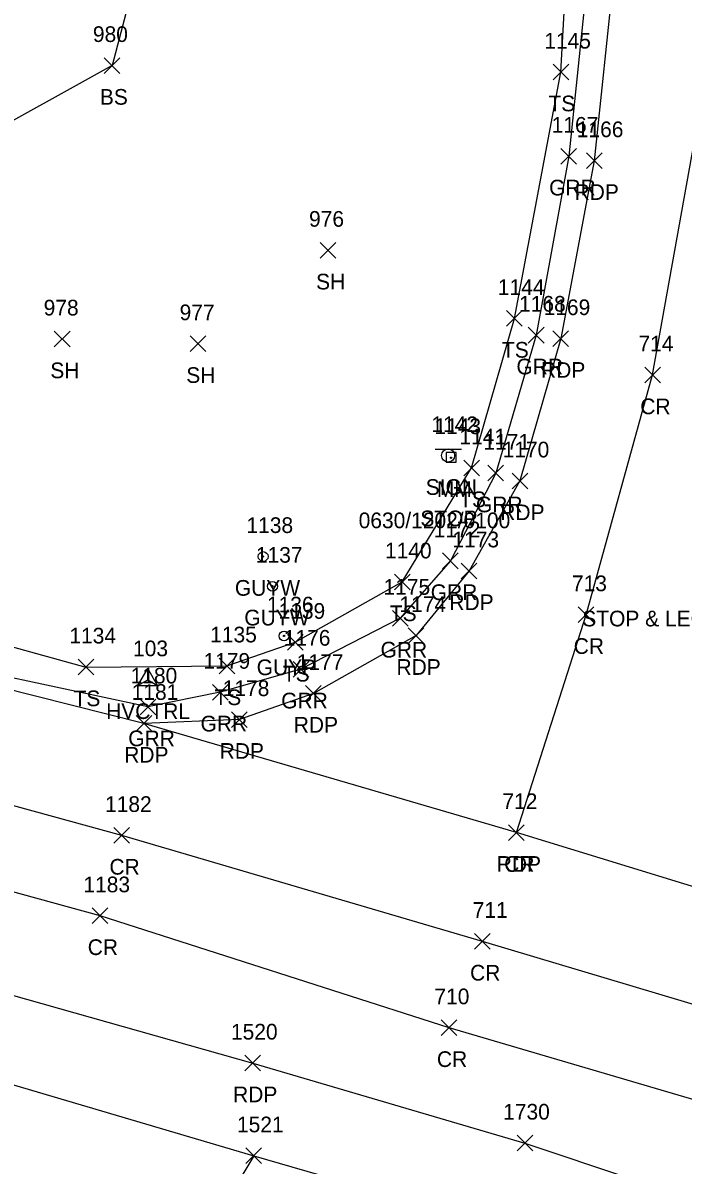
# Model space of a CAD drawing. Extents: x 1629176 to 1637209, y 606063 to 610167.
# Drawn here: x 1629900.9 to 1629985.1, y 606927.3 to 607073 of the extents above; entities that cross this region are included whole.
import ezdxf

# ---------------------------------------------------------------- set-up
doc = ezdxf.new("R2010")
doc.units = 0
for name, color, linetype in [('C_A', 7, 'Continuous'), ('C_I', 7, 'Continuous'), ('CPSM', 7, 'Continuous'), ('L_A', 7, 'Continuous'), ('L_I', 7, 'Continuous'), ('L_TIC', 7, 'Continuous'), ('LELB', 7, 'Continuous'), ('P_A', 7, 'Continuous'), ('P_I', 7, 'Continuous'), ('P_TIC', 7, 'Continuous'), ('PET', 7, 'Continuous'), ('PRC', 7, 'Continuous'), ('PSP', 7, 'Continuous'), ('R_A', 7, 'Continuous'), ('R_I', 7, 'Continuous'), ('R_TIC', 7, 'Continuous'), ('RGR', 7, 'Continuous'), ('S_A', 7, 'Continuous'), ('S_C', 7, 'Continuous'), ('S_I', 7, 'Continuous'), ('SRM', 7, 'Continuous'), ('SSGN', 7, 'Continuous'), ('U_A', 7, 'Continuous'), ('U_I', 7, 'Continuous'), ('UPGW', 7, 'Continuous')]:
    doc.layers.add(name, color=color, linetype=linetype)

msp = doc.modelspace()

# ---------------------------------------------------------------- linework, layer by layer
at = {"layer": 'CPSM'}
for p, q in [((1629915.61, 606988.49), (1629916.86, 606990.66)), ((1629918.11, 606988.49), (1629916.86, 606990.66)), ((1629916.86, 606989.22), (1629916.86, 606990.66)), ((1629915.61, 606988.49), (1629916.86, 606989.22)), ((1629915.61, 606988.49), (1629918.11, 606988.49)), ((1629916.86, 606989.22), (1629916.86, 606989.22)), ((1629916.86, 606989.22), (1629918.11, 606988.49))]:
    msp.add_line(p, q, dxfattribs=at)
at = {"layer": 'L_TIC'}
for points in [[(1629911.31, 607066.56), (1629913.31, 607068.56)], [(1629913.31, 607066.56), (1629911.31, 607068.56)], [(1629968.56, 607065.72), (1629970.56, 607067.72)], [(1629970.56, 607065.72), (1629968.56, 607067.72)], [(1629938.84, 607043), (1629940.84, 607045)], [(1629940.84, 607043), (1629938.84, 607045)], [(1629962.63, 607034.3), (1629964.63, 607036.3)], [(1629964.63, 607034.3), (1629962.63, 607036.3)], [(1629904.94, 607031.68), (1629906.94, 607033.68)], [(1629906.94, 607031.68), (1629904.94, 607033.68)], [(1629922.28, 607031.08), (1629924.28, 607033.08)], [(1629924.28, 607031.08), (1629922.28, 607033.08)], [(1629957.17, 607015.23), (1629959.17, 607017.23)], [(1629959.17, 607015.23), (1629957.17, 607017.23)], [(1629948.32, 607000.7), (1629950.32, 607002.7)], [(1629950.32, 607000.7), (1629948.32, 607002.7)], [(1629934.68, 606993), (1629936.68, 606995)], [(1629936.68, 606993), (1629934.68, 606995)], [(1629907.98, 606989.85), (1629909.98, 606991.85)], [(1629909.98, 606989.85), (1629907.98, 606991.85)], [(1629925.95, 606989.99), (1629927.95, 606991.99)], [(1629927.95, 606989.99), (1629925.95, 606991.99)]]:
    msp.add_lwpolyline(points, dxfattribs=at)
at = {"layer": 'LELB'}
for points in [[(1629872.74, 607605.4), (1629887.91, 607617.06), (1629901.2, 607617.32), (1629908.5, 607605.8), (1629913.9, 607581.78), (1629917.02, 607546.87), (1629916.16, 607509.81), (1629923.16, 607493.27), (1629925.16, 607453.58), (1629924.47, 607424.14), (1629903.61, 607389.66), (1629905.12, 607348.76), (1629905.7, 607299.56), (1629903.23, 607230.04), (1629906.81, 607190.46), (1629918.09, 607128.12), (1629917.39, 607086.84), (1629912.31, 607067.56), (1629894.57, 607057.72), (1629861.26, 607071.43), (1629823.99, 607082.84), (1629794.36, 607095.25), (1629802.79, 607128.03), (1629840.82, 607119.34)], [(1629543.77, 607066.01), (1629589.78, 607058.79), (1629633.94, 607051.49), (1629688.19, 607049.24), (1629712.27, 607039.3), (1629750.85, 607029.57), (1629792.88, 607021.01), (1629837.09, 607010.22), (1629873.61, 607000.62), (1629908.98, 606990.85), (1629926.95, 606990.99), (1629935.68, 606994), (1629949.32, 607001.7), (1629958.17, 607016.23), (1629963.63, 607035.3), (1629969.56, 607066.72), (1629971.34, 607098.85), (1629970.91, 607134.21), (1629967.52, 607170.11), (1629961.69, 607208.82), (1629957.6, 607251.36), (1629951.48, 607294.54)]]:
    msp.add_lwpolyline(points, dxfattribs=at)
at = {"layer": 'P_TIC'}
for points in [[(1629972.81, 607054.42), (1629974.81, 607056.42)], [(1629974.81, 607054.42), (1629972.81, 607056.42)], [(1629968.53, 607031.73), (1629970.53, 607033.73)], [(1629970.53, 607031.73), (1629968.53, 607033.73)], [(1629980.25, 607027.09), (1629982.25, 607029.09)], [(1629982.25, 607027.09), (1629980.25, 607029.09)], [(1629963.33, 607013.58), (1629965.33, 607015.58)], [(1629965.33, 607013.58), (1629963.33, 607015.58)], [(1629956.85, 607002.11), (1629958.85, 607004.11)], [(1629958.85, 607002.11), (1629956.85, 607004.11)], [(1629971.76, 606996.52), (1629973.76, 606998.52)], [(1629973.76, 606996.52), (1629971.76, 606998.52)], [(1629950.09, 606993.85), (1629952.09, 606995.85)], [(1629952.09, 606993.85), (1629950.09, 606995.85)], [(1629936.99, 606986.48), (1629938.99, 606988.48)], [(1629938.99, 606986.48), (1629936.99, 606988.48)], [(1629915.37, 606982.66), (1629917.37, 606984.66)], [(1629917.37, 606982.66), (1629915.37, 606984.66)], [(1629915.37, 606982.66), (1629917.37, 606984.66)], [(1629917.37, 606982.66), (1629915.37, 606984.66)], [(1629927.54, 606983.14), (1629929.54, 606985.14)], [(1629929.54, 606983.14), (1629927.54, 606985.14)], [(1629962.88, 606968.73), (1629964.88, 606970.73)], [(1629964.88, 606968.73), (1629962.88, 606970.73)], [(1629962.88, 606968.73), (1629964.88, 606970.73)], [(1629964.88, 606968.73), (1629962.88, 606970.73)], [(1629912.54, 606968.37), (1629914.54, 606970.37)], [(1629914.54, 606968.37), (1629912.54, 606970.37)], [(1629909.77, 606958.12), (1629911.77, 606960.12)], [(1629911.77, 606958.12), (1629909.77, 606960.12)], [(1629958.54, 606954.86), (1629960.54, 606956.86)], [(1629960.54, 606954.86), (1629958.54, 606956.86)], [(1629954.3, 606943.84), (1629956.3, 606945.84)], [(1629956.3, 606943.84), (1629954.3, 606945.84)], [(1629929.25, 606939.34), (1629931.25, 606941.34)], [(1629931.25, 606939.34), (1629929.25, 606941.34)], [(1629963.97, 606929.13), (1629965.97, 606931.13)], [(1629965.97, 606929.13), (1629963.97, 606931.13)], [(1629929.37, 606927.51), (1629931.37, 606929.51)], [(1629931.37, 606927.51), (1629929.37, 606929.51)], [(1629929.37, 606927.51), (1629931.37, 606929.51)], [(1629931.37, 606927.51), (1629929.37, 606929.51)]]:
    msp.add_lwpolyline(points, dxfattribs=at)
at = {"layer": 'PET'}
for points in [[(1629946.3, 607384.48), (1629952.98, 607332.78), (1629958.23, 607294.73), (1629964.22, 607247.29), (1629968.92, 607209.69), (1629973.36, 607169.44), (1629976.37, 607135.45), (1629977.25, 607104.98), (1629976.31, 607079.35), (1629973.81, 607055.42), (1629969.53, 607032.73), (1629964.33, 607014.58), (1629957.85, 607003.11), (1629951.09, 606994.85), (1629937.99, 606987.48), (1629928.54, 606984.14), (1629916.37, 606983.66)], [(1630115.59, 606918.47), (1630070.26, 606934.37), (1630047.19, 606942.61), (1630027.81, 606949.5), (1629999.64, 606958.79), (1629963.88, 606969.73), (1629916.37, 606983.66), (1629883.8, 606991.87), (1629841.7, 607003.38), (1629794.53, 607014.94), (1629751.13, 607024.85), (1629703.98, 607035.26), (1629666.74, 607043.02), (1629621.43, 607051.04), (1629588.28, 607056.93), (1629542.89, 607063.67), (1629493.94, 607070.34), (1629447.94, 607075.86), (1629406.53, 607080.22), (1629360.37, 607084.28), (1629316.73, 607087.48), (1629269.81, 607090.12), (1629227.29, 607092.24), (1629182.92, 607093.47)], [(1629181.97, 607055.08), (1629220.58, 607054.17), (1629264.89, 607052.3), (1629300.55, 607050.62), (1629344.63, 607047.49), (1629382.7, 607044.36), (1629427.5, 607039.91), (1629466.96, 607035.43), (1629507.21, 607030.19), (1629538.75, 607025.9), (1629578.99, 607019.69), (1629624.23, 607012.05), (1629673.21, 607003.11), (1629718.04, 606993.87), (1629764.48, 606983.46), (1629805.04, 606973.93), (1629842.82, 606964.4), (1629884.8, 606953.15), (1629930.25, 606940.34), (1629964.97, 606930.13), (1630005.89, 606916.45), (1630050.76, 606901.68), (1630096.23, 606885.67)]]:
    msp.add_lwpolyline(points, dxfattribs=at)
at = {"layer": 'PRC'}
for points in [[(1629963.88, 606969.73), (1629972.76, 606997.52), (1629981.25, 607028.09), (1629988.12, 607066.47), (1629990.62, 607100.29), (1629990.61, 607124.69), (1629989.69, 607149.78), (1629986.77, 607182.68), (1629981.28, 607228.24), (1629975.13, 607276.5), (1629968.07, 607326.63), (1629961.78, 607372.25), (1629956.91, 607408.66), (1629951.88, 607446.34), (1629946.39, 607483.34), (1629940.59, 607526.71), (1629934.53, 607569.1), (1629928.23, 607613.94), (1629922.81, 607653.99), (1629916.48, 607702.82)], [(1630110.18, 606905.77), (1630065.36, 606921.68), (1630022.36, 606935.68), (1629994.71, 606945.36), (1629959.54, 606955.86), (1629913.54, 606969.37), (1629877.41, 606979.26), (1629837.69, 606989.99), (1629791.63, 607000.82), (1629746.42, 607011.44), (1629699.59, 607021.37), (1629664.04, 607028.34), (1629619.43, 607036.79), (1629585.72, 607042.18), (1629539.96, 607049.3), (1629491.45, 607056.02), (1629445.88, 607061.28), (1629404.36, 607066.23), (1629358.89, 607069.49), (1629314.63, 607073.29), (1629269.37, 607075.36), (1629226.58, 607077.32), (1629182.35, 607078.58)], [(1630105.99, 606894.95), (1630061.18, 606910.94), (1630017.61, 606925.74), (1629991.01, 606934.32), (1629955.3, 606944.84), (1629910.77, 606959.12), (1629874.52, 606969.06), (1629834.93, 606979.4), (1629788.74, 606990.13), (1629743.3, 607000.68), (1629697.98, 607010.33), (1629662.17, 607017.56), (1629618.2, 607025.81), (1629583.59, 607031.56), (1629540.4, 607037.95), (1629489.63, 607045.02), (1629444.26, 607050.14), (1629402.79, 607054.66), (1629359.1, 607058.26), (1629313.06, 607061.88), (1629268.47, 607063.97), (1629226.23, 607065.89), (1629182.22, 607066.96)], [(1629930.37, 606928.51), (1629922.33, 606915.08), (1629903.69, 606892.32), (1629888.42, 606875.5), (1629871.3, 606859.39), (1629850.1, 606843.52), (1629825.75, 606829.77), (1629796.32, 606815.42), (1629774.04, 606806.57), (1629748.19, 606798.61), (1629722.01, 606792.8), (1629693.98, 606789.27), (1629667.56, 606787.71), (1629632.27, 606787.81), (1629586.9, 606789.65)]]:
    msp.add_lwpolyline(points, dxfattribs=at)
at = {"layer": 'PSP'}
msp.add_lwpolyline([(1629181.26, 607044.82), (1629219.33, 607043.61), (1629263.7, 607041.6), (1629300.14, 607039.68), (1629342.49, 607036.76), (1629381.41, 607033.8), (1629425.61, 607029.43), (1629465.11, 607025.03), (1629505.36, 607019.79), (1629537.56, 607015.39), (1629576.08, 607009.38), (1629623.28, 607001.72), (1629671.03, 606992.73), (1629715.19, 606983.38), (1629761.23, 606973.52), (1629802.25, 606963.72), (1629839.3, 606954.1), (1629871.33, 606945.94), (1629930.37, 606928.51), (1629965.2, 606918.43), (1630003.07, 606906.25), (1630045.28, 606892.75), (1630092.08, 606875.64)], dxfattribs=at)
at = {"layer": 'R_TIC'}
for points in [[(1629969.56, 607054.99), (1629971.56, 607056.99)], [(1629971.56, 607054.99), (1629969.56, 607056.99)], [(1629965.4, 607032.17), (1629967.4, 607034.17)], [(1629967.4, 607032.17), (1629965.4, 607034.17)], [(1629960.24, 607014.58), (1629962.24, 607016.58)], [(1629962.24, 607014.58), (1629960.24, 607016.58)], [(1629954.46, 607003.39), (1629956.46, 607005.39)], [(1629956.46, 607003.39), (1629954.46, 607005.39)], [(1629948.06, 606996.06), (1629950.06, 606998.06)], [(1629950.06, 606996.06), (1629948.06, 606998.06)], [(1629935.39, 606989.57), (1629937.39, 606991.57)], [(1629937.39, 606989.57), (1629935.39, 606991.57)], [(1629925.1, 606986.63), (1629927.1, 606988.63)], [(1629927.1, 606986.63), (1629925.1, 606988.63)], [(1629915.88, 606984.75), (1629917.88, 606986.75)], [(1629917.88, 606984.75), (1629915.88, 606986.75)]]:
    msp.add_lwpolyline(points, dxfattribs=at)
at = {"layer": 'RGR'}
msp.add_lwpolyline([(1629943.69, 607384.05), (1629950.32, 607332.08), (1629955.32, 607294.81), (1629961.02, 607247.36), (1629965.35, 607210.17), (1629970.15, 607169.34), (1629972.95, 607135.74), (1629974.05, 607104.82), (1629973.08, 607080.23), (1629970.56, 607055.99), (1629966.4, 607033.17), (1629961.24, 607015.58), (1629955.46, 607004.39), (1629949.06, 606997.06), (1629936.39, 606990.57), (1629926.1, 606987.63), (1629916.88, 606985.75), (1629884.2, 606992.74), (1629842, 607003.78), (1629794.61, 607015.29), (1629751.3, 607025.15), (1629713.98, 607033.77), (1629702.23, 607037.41), (1629690.41, 607042.59)], dxfattribs=at)
at = {"layer": 'SRM'}
for p, q in [((1629956.19, 607018.21), (1629954.94, 607018.21)), ((1629954.94, 607018.21), (1629954.94, 607016.96)), ((1629956.19, 607018.21), (1629954.94, 607018.21)), ((1629954.94, 607018.21), (1629954.94, 607016.96)), ((1629956.19, 607016.96), (1629956.19, 607018.21)), ((1629956.19, 607016.96), (1629956.19, 607018.21)), ((1629954.94, 607016.96), (1629956.19, 607016.96)), ((1629954.94, 607016.96), (1629956.19, 607016.96))]:
    msp.add_line(p, q, dxfattribs=at)
msp.add_circle((1629955.54, 607017.54), 0.0833, dxfattribs=at)
at = {"layer": 'SSGN'}
for p, q in [((1629953.52, 607018.65), (1629956.86, 607018.65)), ((1629955.17, 607017.82), (1629955.17, 607017.82))]:
    msp.add_line(p, q, dxfattribs=at)
msp.add_circle((1629955.17, 607017.82), 0.833, dxfattribs=at)
at = {"layer": 'UPGW'}
for centre, radius in [((1629931.58, 607004.94), 0.625), ((1629931.58, 607004.94), 0.0833), ((1629932.77, 607001.15), 0.625), ((1629932.77, 607001.15), 0.0833), ((1629934.24, 606994.81), 0.625), ((1629934.24, 606994.81), 0.0833)]:
    msp.add_circle(centre, radius, dxfattribs=at)

# ---------------------------------------------------------------- texts
at = {"layer": 'C_A'}
msp.add_text('HVCTRL', height=2, dxfattribs=at).set_placement((1629911.55, 606984.22))
at = {"layer": 'C_I'}
msp.add_text('103', height=2, dxfattribs=at).set_placement((1629914.98, 606992.22))
at = {"layer": 'L_A'}
for s, p in [('BS', (1629910.75, 607062.56)), ('TS', (1629967.97, 607061.72)), ('SH', (1629938.33, 607039)), ('TS', (1629962.04, 607030.3)), ('SH', (1629904.43, 607027.68)), ('SH', (1629921.77, 607027.08)), ('TS', (1629956.58, 607011.23)), ('TS', (1629947.73, 606996.7)), ('TS', (1629934.08, 606989)), ('TS', (1629907.39, 606985.85)), ('TS', (1629925.36, 606985.99))]:
    msp.add_text(s, height=2, dxfattribs=at).set_placement(p)
at = {"layer": 'L_I'}
for s, p in [('980', (1629909.86, 607070.56)), ('1145', (1629967.43, 607069.72)), ('976', (1629937.43, 607047)), ('1144', (1629961.51, 607038.3)), ('978', (1629903.58, 607035.68)), ('977', (1629920.92, 607035.08)), ('1141', (1629956.61, 607019.23)), ('1140', (1629947.11, 607004.7)), ('1139', (1629933.54, 606997)), ('1134', (1629906.86, 606993.85)), ('1135', (1629924.82, 606993.99))]:
    msp.add_text(s, height=2, dxfattribs=at).set_placement(p)
at = {"layer": 'P_A'}
for s, p in [('RDP', (1629971.3, 607050.42)), ('RDP', (1629967.02, 607027.73)), ('CR', (1629979.68, 607023.09)), ('RDP', (1629961.82, 607009.58)), ('RDP', (1629955.33, 606998.11)), ('CR', (1629971.19, 606992.52)), ('RDP', (1629948.58, 606989.85)), ('RDP', (1629935.48, 606982.48)), ('RDP', (1629926.03, 606979.14)), ('RDP', (1629913.86, 606978.66)), ('RDP', (1629913.86, 606978.66)), ('CR', (1629911.97, 606964.37)), ('RDP', (1629961.37, 606964.73)), ('CR', (1629962.32, 606964.73)), ('CR', (1629909.2, 606954.12)), ('CR', (1629957.97, 606950.86)), ('CR', (1629953.74, 606939.84)), ('RDP', (1629927.74, 606935.34))]:
    msp.add_text(s, height=2, dxfattribs=at).set_placement(p)
at = {"layer": 'P_I'}
for s, p in [('1166', (1629971.58, 607058.42)), ('1169', (1629967.35, 607035.73)), ('714', (1629979.45, 607031.09)), ('1170', (1629962.12, 607017.58)), ('1173', (1629955.72, 607006.11)), ('713', (1629970.96, 607000.52)), ('1174', (1629948.96, 606997.85)), ('1177', (1629935.87, 606990.48)), ('1181', (1629914.81, 606986.66)), ('1181', (1629914.81, 606986.66)), ('1178', (1629926.42, 606987.14)), ('1182', (1629911.41, 606972.37)), ('712', (1629962.09, 606972.73)), ('712', (1629962.09, 606972.73)), ('1183', (1629908.65, 606962.12)), ('711', (1629958.31, 606958.86)), ('710', (1629953.42, 606947.84)), ('1520', (1629927.47, 606943.34)), ('1730', (1629962.19, 606933.13)), ('1521', (1629928.24, 606931.51)), ('1521', (1629928.24, 606931.51))]:
    msp.add_text(s, height=2, dxfattribs=at).set_placement(p)
at = {"layer": 'R_A'}
for p in [(1629968.05, 607050.99), (1629963.88, 607028.17), (1629958.72, 607010.58), (1629952.95, 606999.39), (1629946.55, 606992.06), (1629933.88, 606985.57), (1629923.59, 606982.63), (1629914.37, 606980.75)]:
    msp.add_text('GRR', height=2, dxfattribs=at).set_placement(p)
at = {"layer": 'R_I'}
for s, p in [('1167', (1629968.38, 607058.99)), ('1168', (1629964.22, 607036.17)), ('1171', (1629959.68, 607018.58)), ('1172', (1629953.33, 607007.39)), ('1175', (1629946.93, 607000.06)), ('1176', (1629934.21, 606993.57)), ('1179', (1629923.97, 606990.63)), ('1180', (1629914.67, 606988.75))]:
    msp.add_text(s, height=2, dxfattribs=at).set_placement(p)
at = {"layer": 'S_A'}
for s, p in [('SIGN', (1629952.31, 607012.8)), ('MM', (1629953.73, 607012.55))]:
    msp.add_text(s, height=2, dxfattribs=at).set_placement(p)
at = {"layer": 'S_C'}
for s, p in [('0630/1202/0100', (1629943.76, 607008.55)), ('STOP', (1629951.63, 607008.8)), ('STOP & LEGAL LOAD LIMIT 24000 LB', (1629972.28, 606996.03))]:
    msp.add_text(s, height=2, dxfattribs=at).set_placement(p)
at = {"layer": 'S_I'}
for s, p in [('1142', (1629953.03, 607020.8)), ('1143', (1629953.42, 607020.55))]:
    msp.add_text(s, height=2, dxfattribs=at).set_placement(p)
at = {"layer": 'U_A'}
for s, p in [('GUYW', (1629927.97, 606999.94)), ('GUYW', (1629929.17, 606996.15)), ('GUYP', (1629930.75, 606989.81))]:
    msp.add_text(s, height=2, dxfattribs=at).set_placement(p)
at = {"layer": 'U_I'}
for s, p in [('1138', (1629929.45, 607007.94)), ('1137', (1629930.65, 607004.15)), ('1136', (1629932.06, 606997.81))]:
    msp.add_text(s, height=2, dxfattribs=at).set_placement(p)

doc.saveas('drawing.dxf')
